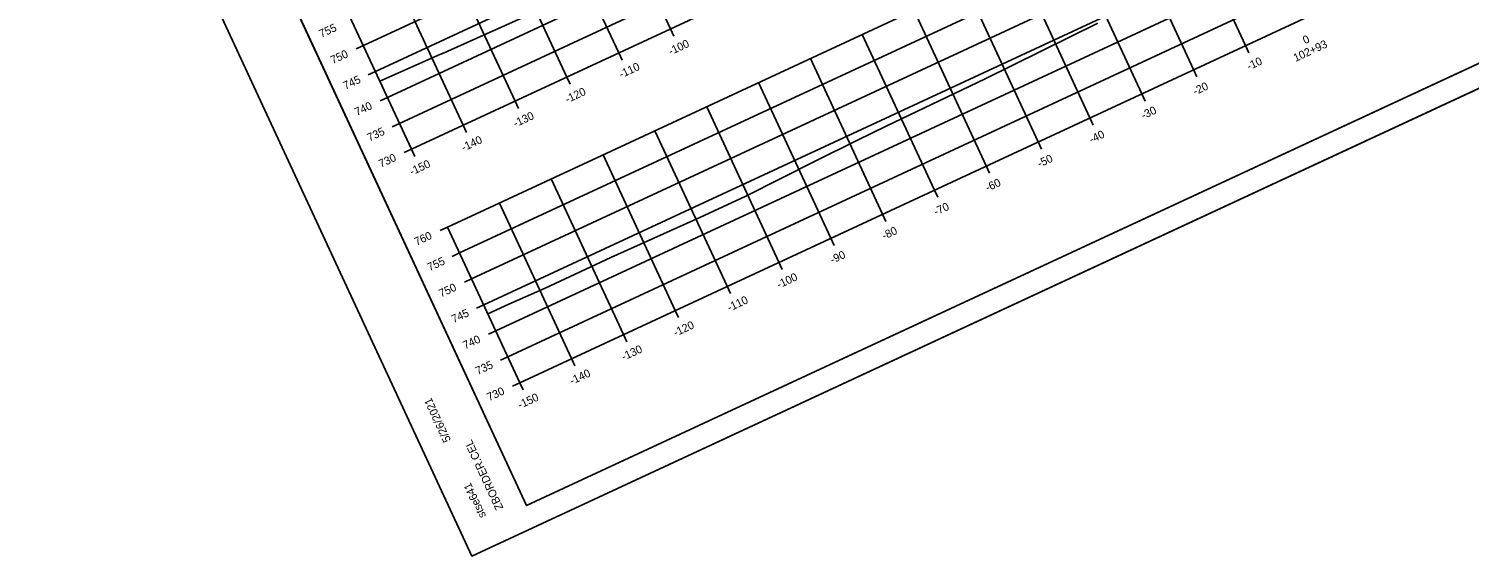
# Model space of a CAD drawing. Extents: x 1354696 to 1366163, y 660729 to 670380.
# Drawn here: x 1356702.3 to 1356954.3, y 664651.1 to 664743.4 of the extents above; entities that cross this region are included whole.
import ezdxf

# ---------------------------------------------------------------- set-up
doc = ezdxf.new("R2010")
doc.units = 0
for name, color, linetype in [('R_Axis', 7, 'Continuous'), ('R_Axis Annot', 7, 'Continuous'), ('R_Border', 7, 'Continuous'), ('R_Exist Surface', 7, 'Continuous'), ('R_Grid', 7, 'Continuous'), ('R_No Plot', 7, 'Continuous')]:
    doc.layers.add(name, color=color, linetype=linetype)

msp = doc.modelspace()

# ---------------------------------------------------------------- linework, layer by layer
at = {"layer": 'R_Axis'}
for p, q in [((1356769.23, 664722.3), (1357041.34, 664848.63)), ((1356788.18, 664681.48), (1357060.29, 664807.81)), ((1356769.23, 664722.3), (1356756.6, 664749.51)), ((1356815.17, 664742.08), (1356814.58, 664743.35)), ((1356759.54, 664739.85), (1356760.81, 664740.44)), ((1356915.75, 664739.17), (1356915.16, 664740.44)), ((1356806.1, 664737.87), (1356805.51, 664739.14)), ((1356761.65, 664735.31), (1356762.92, 664735.9)), ((1356906.68, 664734.96), (1356906.09, 664736.23)), ((1356797.03, 664733.66), (1356796.44, 664734.93)), ((1356763.75, 664730.78), (1356765.02, 664731.37)), ((1356787.96, 664729.45), (1356787.37, 664730.72)), ((1356897.61, 664730.74), (1356897.02, 664732.01)), ((1356888.54, 664726.53), (1356887.95, 664727.8)), ((1356765.86, 664726.24), (1356767.13, 664726.83)), ((1356778.89, 664725.24), (1356778.3, 664726.51)), ((1356879.47, 664722.32), (1356878.88, 664723.59)), ((1356767.96, 664721.71), (1356769.23, 664722.3)), ((1356769.82, 664721.03), (1356769.23, 664722.3)), ((1356870.4, 664718.11), (1356869.81, 664719.38)), ((1356861.33, 664713.9), (1356860.74, 664715.17)), ((1356852.26, 664709.69), (1356851.67, 664710.96)), ((1356774.28, 664708.1), (1356775.55, 664708.69)), ((1356788.18, 664681.48), (1356775.55, 664708.69)), ((1356843.19, 664705.48), (1356842.6, 664706.75)), ((1356776.38, 664703.57), (1356777.65, 664704.16)), ((1356834.12, 664701.27), (1356833.53, 664702.54)), ((1356778.49, 664699.03), (1356779.76, 664699.62)), ((1356825.05, 664697.06), (1356824.46, 664698.33)), ((1356780.6, 664694.5), (1356781.87, 664695.09)), ((1356815.98, 664692.85), (1356815.39, 664694.12)), ((1356782.7, 664689.96), (1356783.97, 664690.55)), ((1356806.91, 664688.63), (1356806.32, 664689.9)), ((1356784.81, 664685.43), (1356786.08, 664686.02)), ((1356797.84, 664684.42), (1356797.25, 664685.69)), ((1356786.91, 664680.89), (1356788.18, 664681.48)), ((1356788.77, 664680.21), (1356788.18, 664681.48))]:
    msp.add_line(p, q, dxfattribs=at)
at = {"layer": 'R_Border'}
for p, q in [((1356789.35, 664659.97), (1356702.83, 664846.33)), ((1357076.13, 664793.12), (1356789.35, 664659.97)), ((1356789.35, 664659.97), (1356789.35, 664659.97))]:
    msp.add_line(p, q, dxfattribs=at)
at = {"layer": 'R_Exist Surface'}
for points in [[(1356763.71, 664734.2), (1356774.18, 664738.86), (1356775.23, 664739.31), (1356775.6, 664739.48), (1356800.95, 664750.89)], [(1356782.6, 664693.5), (1356786.24, 664695.19), (1356792.61, 664698.03), (1356804.12, 664703.36), (1356819.7, 664710.37), (1356827.72, 664714.1), (1356839.74, 664720.14), (1356847.28, 664723.89), (1356852.27, 664726.32), (1356869.6, 664734.63), (1356889.32, 664744.33)]]:
    msp.add_lwpolyline(points, dxfattribs=at)
at = {"layer": 'R_Grid'}
for p, q in [((1356760.81, 664740.44), (1357032.91, 664866.77)), ((1356762.92, 664735.9), (1357035.02, 664862.23)), ((1356765.02, 664731.37), (1357037.13, 664857.7)), ((1356767.13, 664726.83), (1357039.23, 664853.16)), ((1356769.23, 664722.3), (1357041.34, 664848.63)), ((1356775.55, 664708.69), (1357047.65, 664835.02)), ((1356777.65, 664704.16), (1357049.76, 664830.49)), ((1356779.76, 664699.62), (1357051.86, 664825.95)), ((1356781.87, 664695.09), (1357053.97, 664821.42)), ((1356783.97, 664690.55), (1357056.08, 664816.88)), ((1356786.08, 664686.02), (1357058.18, 664812.35)), ((1356788.18, 664681.48), (1357060.29, 664807.81)), ((1356814.58, 664743.35), (1356801.95, 664770.56)), ((1356805.51, 664739.14), (1356792.88, 664766.35)), ((1356915.16, 664740.44), (1356902.53, 664767.65)), ((1356906.09, 664736.23), (1356893.46, 664763.44)), ((1356796.44, 664734.93), (1356783.81, 664762.14)), ((1356787.37, 664730.72), (1356774.74, 664757.93)), ((1356897.02, 664732.01), (1356884.39, 664759.22)), ((1356778.3, 664726.51), (1356765.67, 664753.72)), ((1356887.95, 664727.8), (1356875.32, 664755.01)), ((1356878.88, 664723.59), (1356866.25, 664750.8)), ((1356769.23, 664722.3), (1356756.6, 664749.51)), ((1356869.81, 664719.38), (1356857.18, 664746.59)), ((1356860.74, 664715.17), (1356848.11, 664742.38)), ((1356851.67, 664710.96), (1356839.04, 664738.17)), ((1356842.6, 664706.75), (1356829.97, 664733.96)), ((1356833.53, 664702.54), (1356820.9, 664729.75)), ((1356824.46, 664698.33), (1356811.83, 664725.54)), ((1356815.39, 664694.12), (1356802.76, 664721.33)), ((1356806.32, 664689.9), (1356793.69, 664717.11)), ((1356797.25, 664685.69), (1356784.62, 664712.9)), ((1356788.18, 664681.48), (1356775.55, 664708.69))]:
    msp.add_line(p, q, dxfattribs=at)
at = {"layer": 'R_No Plot'}
msp.add_line((1356779.78, 664651.14), (1357082.11, 664791.51), dxfattribs=at)
for points in [[(1356689.93, 664844.64), (1356992.28, 664985.01), (1357082.12, 664791.51), (1356779.77, 664651.14)], [(1356915, 664944.83), (1356932.79, 664953.09), (1356936.95, 664944.13), (1356951.57, 664950.92), (1356972.61, 664960.69), (1356984.58, 664935.2), (1357005.63, 664944.97), (1357076.13, 664793.12), (1356789.35, 664659.97), (1356702.83, 664846.33)]]:
    msp.add_lwpolyline(points, close=True, dxfattribs=at)

# ---------------------------------------------------------------- texts
at = {"layer": 'R_Axis Annot'}
for s, p in [('755', (1356753.46, 664741.77)), ('-100', (1356814.59, 664738.72)), ('102+93', (1356923.94, 664737.56)), ('0', (1356925.59, 664740.65)), ('750', (1356755.46, 664737.18)), ('-10', (1356915.79, 664736.1)), ('745', (1356757.67, 664732.7)), ('-110', (1356805.93, 664734.7)), ('-120', (1356796.5, 664730.33)), ('-20', (1356906.36, 664731.72)), ('740', (1356759.67, 664728.11)), ('-130', (1356787.43, 664726.11)), ('-30', (1356897.29, 664727.51)), ('735', (1356761.88, 664723.63)), ('-40', (1356888.22, 664723.3)), ('-140', (1356778.36, 664721.9)), ('730', (1356763.88, 664719.04)), ('-150', (1356769.29, 664717.69)), ('-50', (1356879.15, 664719.08)), ('-60', (1356870.05, 664714.86)), ('-70', (1356861.01, 664710.66)), ('760', (1356770.13, 664705.41)), ('-80', (1356851.94, 664706.45)), ('755', (1356772.41, 664700.95)), ('-90', (1356842.87, 664702.24)), ('-100', (1356833.54, 664697.91)), ('750', (1356774.41, 664696.36)), ('-110', (1356824.88, 664693.89)), ('745', (1356776.62, 664691.88)), ('-120', (1356815.45, 664689.51)), ('740', (1356778.62, 664687.29)), ('-130', (1356806.38, 664685.3)), ('735', (1356780.83, 664682.81)), ('-140', (1356797.31, 664681.09)), ('730', (1356782.83, 664678.22)), ('-150', (1356788.24, 664676.88))]:
    msp.add_text(s, height=1.4, rotation=24.9042, dxfattribs=at).set_placement(p)
at = {"layer": 'R_Border'}
for s, p in [('5/26/2021', (1356776.17, 664671.42)), ('ZBORDER.CEL', (1356785.34, 664659.57)), ('stse641', (1356782.32, 664658.17))]:
    msp.add_text(s, height=1.4, rotation=114.9042, dxfattribs=at).set_placement(p)

doc.saveas('drawing.dxf')
